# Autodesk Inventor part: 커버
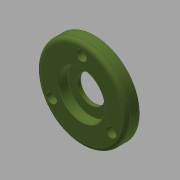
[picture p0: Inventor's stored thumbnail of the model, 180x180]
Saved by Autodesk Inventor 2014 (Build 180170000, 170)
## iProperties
Created: 2016-06
Part Number: 커버
Material: 알루미늄 6061
Document SubType Name: Modeling
Designer: mduedu
Density: 2.71 g/cm^3
Appearance: Olive Green
Author: mduedu
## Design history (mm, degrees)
sketch "스케치1"
  geometry: C1 r 34 at (0, 0); 1 further point
  constraints: 1 centre point, 1 coincident
  dimensions: "d0" = 68 diameter of C1
extrude "돌출1" new body sketch "스케치1" distance "d2" = 10; taper "d3" = 0 deg
sketch "스케치2"
  geometry: C1 r 21 at (0, 0); 1 further point
  constraints: 1 centre point, 1 coincident
  dimensions: "d4" = 42 diameter of C1
extrude "돌출2" join sketch "스케치2" distance "d6" = 3; taper "d7" = 0 deg
fillet "모깎기1" dims "d8" = 3
hole "구멍1" diameter "d11" = 35; stored, may be unused: countersink angle "d15" = 90 deg, drill point angle "d17" = 0 deg; dims "d9" = 10, "d10" = 10, "d12" = 6, "d13" = 4, "d14" = 2, "d16" = 3
hole "구멍2" diameter "d20" = 35; stored, may be unused: countersink angle "d24" = 90 deg, drill point angle "d26" = 0 deg; dims "d21" = 6, "d22" = 4, "d23" = 2, "d25" = 7.3, "d73" = 10, "d74" = 10
hole "구멍3" diameter "d29" = 21; stored, may be unused: countersink angle "d33" = 90 deg, drill point angle "d35" = 0 deg; dims "d27" = 10, "d28" = 10, "d30" = 6, "d31" = 4, "d32" = 2, "d34" = 5
fillet "모깎기2" dims "d36" = 3
fillet "모깎기3" dims "d37" = 0.1
chamfer "모따기1" distance "d38" = 0.7; stored, may be unused: second distance "d39" = 2, angle "d40" = 30 deg
chamfer "모따기2" distance "d42" = 0.5; stored, may be unused: second distance "d43" = 2, angle "d44" = 30 deg
sketch "스케치5" dims "d60" = 52
  geometry: 3 further points
  constraints: 2 vertical alignment, 1 coincident, 2 other
hole "구멍5" sketch "스케치5" at (0, 26) diameter "d61" = 4.5; stored, may be unused: countersink angle "d65" = 90 deg, drill point angle "d67" = 118 deg; dims "d62" = 6, "d63" = 8, "d64" = 4.6, "d66" = 8
node "솔리드1"
pattern_circular "원형 패턴1" dims angle "d69" = 360 deg
